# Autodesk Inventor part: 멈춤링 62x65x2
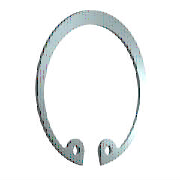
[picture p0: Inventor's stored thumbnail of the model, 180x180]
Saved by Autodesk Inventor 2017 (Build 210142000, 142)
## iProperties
IsCustomPart: 1
Created: 2012-02
Part Number: 멈춤링 62x65x2
Material: 강철, 연강
Description: 스프링 리테이닝 링
Document SubType Name: Modeling
Standard: JIS B 2804
Designer: mdu
Standards Organization: JIS
Language: ko-KR
Size Designation: 62x2
Categories: <MemberInstance><Categories><Category DisplayName="샤프트 부품" InternalName="7f7aeb1f-a693-4053-b835-cee3144e0d98" Mnemonic="SHFT"><Category DisplayName="써클립" Inter
Density: 1 g/cm^3
Appearance: 강철
Author: mdu
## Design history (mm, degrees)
sketch "스케치1"
  geometry: L1 (0, 15.113)-(0, -73.177) reference; L2 (-45.5, 0)-(45.5, 0) reference; L3 (-4.964, 1.5)-(1.502, 1.5); L4 (0, -4)-(-5.307, -4); L5 (0, -31)-(-13.368, -60.623); L6 (-13.368, -60.623)-(-26.939, -54.499); L7 (-11.949, -57.479)-(-22.5, -52.717); L8 (-9.671, -58.507)-(-11.05, -61.564); L9 (9.671, -58.507)-(11.05, -61.564); C1 r 1.25 at (-11.949, -57.479); C2 r 1.25 at (11.949, -57.479); A1 r 28.375 centre (0, -32.375) between (16.406, -55.527) and (-16.406, -55.527); A2 r 32.5 centre (0, -31) between (11.05, -61.564) and (-11.05, -61.564); A3 r 2.5 centre (-11.949, -57.479) between (-9.671, -58.507) and (-13.455, -55.483); A4 r 2.5 centre (-14.96, -53.487) between (-16.406, -55.527) and (-13.455, -55.483); A5 r 2.5 centre (14.96, -53.487) between (13.455, -55.483) and (16.406, -55.527); A6 r 2.5 centre (11.949, -57.479) between (13.455, -55.483) and (9.671, -58.507); 3 further points
  constraints: 15 point on circle, 14 end point, 9 symmetric about line, 8 centre point, 6 tangent, 4 coincident, 4 point on line, 3 perpendicular, 1 parallel, 4 other
  dimensions: "d8" = 1.375 distance of A1.centre L5.start (= 0.25 x SRB1); "d38" = 5.5 distance between parallel lines of L4 L3 (= SRB1); "d39" = 31 distance from line of L5.start L2 (= 0.5 x WD); "d43" = 32.5 radius of A2 (= 0.5 x ND); "d45" = 3.45 distance between parallel lines of L7 L6 (= 0.5 x SRB2); "d46" = 2.5 radius of A4 (= SD5); "d47" = 11.05 distance from line of L1 L8.end (= 0.17 x ND); "d48" = 2.5 diameter of C1 (= SD5); "d49" = 2.5 radius of A3 (= SD5)
extrude "본체" new body sketch "스케치1" distance "d2" = 2 (= SD); taper "d3" = 0 deg
workaxis "Work Axis1"
workaxis "Work Axis2"
workplane "Work Plane1"
node "작업 평면2"
body "Solid1"
other parameters: "WD" = 62 [user parameter; used in 1 equation term], "SD" = 2 [user parameter; used in 1 equation term], "SRB1" = 5.5 [user parameter; used in 2 equation terms], "ND" = 65 [user parameter; used in 2 equation terms], "SRB2" = 6.9 [user parameter; used in 1 equation term], "SD5" = 2.5 [user parameter; used in 3 equation terms], "d50" = 0, "d51" = 0, "d52" = 0, "d53" = 0, "SD6" = 66.2 [user parameter], "WDMAX" = 62 (= NND) [user parameter], "NND" = 62 [user parameter; used in 1 equation term]
